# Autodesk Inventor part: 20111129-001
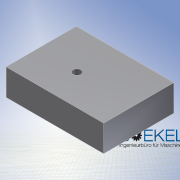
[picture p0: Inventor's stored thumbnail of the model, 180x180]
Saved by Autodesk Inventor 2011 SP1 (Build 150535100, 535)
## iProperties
Created: 2010-11
Part Number: 20111129-001
Document SubType Name: Modeling
Designer: Boekels
Density: 1 g/cm^3
Author: Boekels
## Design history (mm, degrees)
sketch "Skizze1"
  geometry: L1 (0, 0)-(36.904, 0); L2 (36.904, 0)-(36.904, 26.559); L3 (36.904, 26.559)-(0, 26.559); L4 (0, 26.559)-(0, 0)
  constraints: 8 end point, 2 parallel, 1 horizontal, 1 perpendicular
extrude "Extrusion1" new body sketch "Skizze1" distance "d0" = 10; taper "d1" = 0 deg
hole "Hole1" diameter "d4" = 3; stored, may be unused: countersink angle "d8" = 90 deg, drill point angle "d10" = 118 deg; dims "d2" = 11.691, "d3" = 21.781, "d5" = 6, "d6" = 4, "d7" = 2, "d9" = 8
node "Volumenkörper1"
node "Volumenkörpern"
node "Oberflächenkörpern"
